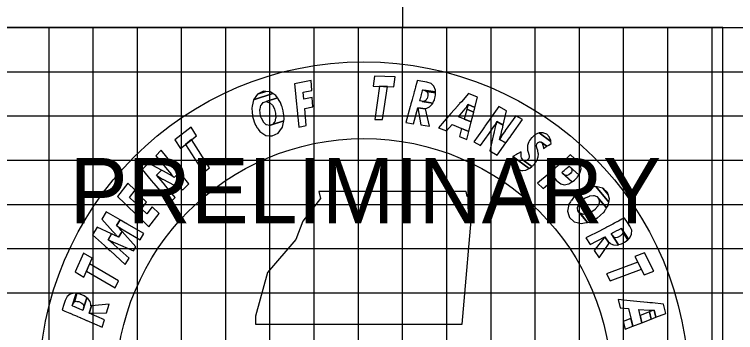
# Model space of a CAD drawing. Extents: x 21502 to 21854, y 6226 to 6446.
# Drawn here: x 21825.23 to 21841.55, y 6426.29 to 6433.48 of the extents above; entities that cross this region are included whole.
import ezdxf

# ---------------------------------------------------------------- set-up
doc = ezdxf.new("R2010")
doc.units = 0
for name, color, linetype in [('SHEET_LOGO', 7, 'Continuous'), ('SHEET_PRELIM', 7, 'Continuous'), ('SHEET_PROJ_NUMBER', 7, 'Continuous'), ('XS_SHEET_MAJOR_GRIDS', 7, 'Continuous'), ('XS_SHEET_MEDIUM_GRIDS', 7, 'Continuous'), ('XS_SHEET_MINOR_GRIDS', 7, 'Continuous')]:
    doc.layers.add(name, color=color, linetype=linetype)

msp = doc.modelspace()

# ---------------------------------------------------------------- linework, layer by layer
at = {"layer": 'SHEET_LOGO'}
for points in [[(21825.014, 6416.944), (21841.256, 6416.944), (21841.256, 6433.186), (21825.014, 6433.186)], [(21833.38, 6432.089), (21833.347, 6431.862), (21833.811, 6431.845), (21833.844, 6432.072)], [(21831.626, 6431.317), (21831.662, 6430.935), (21831.834, 6430.969), (21831.798, 6431.352), (21831.985, 6431.389), (21831.965, 6431.6), (21831.778, 6431.563), (21831.763, 6431.725), (21831.963, 6431.765), (21831.942, 6431.99), (21831.57, 6431.915), (21831.591, 6431.69), (21831.606, 6431.528)], [(21834.186, 6431.399), (21834.088, 6431.036), (21834.261, 6431.008), (21834.358, 6431.372), (21834.528, 6431.345), (21834.525, 6431.358), (21834.564, 6431.365), (21834.622, 6431.391), (21834.684, 6431.452), (21834.697, 6431.477), (21834.399, 6431.524), (21834.401, 6431.532), (21834.408, 6431.558), (21834.418, 6431.591), (21834.422, 6431.606), (21834.438, 6431.667), (21834.438, 6431.667), (21834.45, 6431.71), (21834.449, 6431.711), (21834.453, 6431.722), (21834.462, 6431.757), (21834.466, 6431.772), (21834.467, 6431.774), (21834.756, 6431.729), (21834.756, 6431.77), (21834.721, 6431.859), (21834.658, 6431.921), (21834.564, 6431.951), (21834.469, 6431.967), (21834.344, 6431.986), (21834.344, 6431.986), (21834.34, 6431.971), (21834.327, 6431.922), (21834.305, 6431.841), (21834.294, 6431.802), (21834.294, 6431.799), (21834.289, 6431.784), (21834.28, 6431.749), (21834.277, 6431.738), (21834.265, 6431.694), (21834.249, 6431.634), (21834.245, 6431.619), (21834.236, 6431.585), (21834.229, 6431.559), (21834.227, 6431.552), (21834.22, 6431.525), (21834.202, 6431.457), (21834.193, 6431.424), (21834.189, 6431.411)], [(21833.493, 6431.857), (21833.385, 6431.109), (21833.561, 6431.103), (21833.67, 6431.85)], [(21834.525, 6431.763), (21834.562, 6431.741), (21834.757, 6431.71), (21834.756, 6431.726), (21834.756, 6431.729), (21834.492, 6431.77)], [(21831.016, 6430.737), (21831.065, 6430.733), (21831.199, 6430.797), (21831.235, 6430.848), (21831.293, 6430.93), (21831.308, 6431.004), (21831.323, 6431.073), (21831.001, 6430.967), (21831.001, 6430.967), (21830.937, 6430.983), (21830.93, 6430.985), (21830.928, 6430.986), (21830.866, 6431.044), (21830.865, 6431.046), (21830.863, 6431.049), (21830.818, 6431.132), (21830.817, 6431.136), (21830.815, 6431.141), (21830.791, 6431.23), (21830.79, 6431.235), (21830.79, 6431.239), (21830.786, 6431.335), (21830.787, 6431.339), (21830.788, 6431.341), (21830.809, 6431.426), (21830.81, 6431.426), (21830.818, 6431.436), (21830.861, 6431.487), (21830.928, 6431.51), (21831.182, 6431.593), (21831.147, 6431.645), (21831.078, 6431.691), (21830.637, 6431.547), (21830.622, 6431.473), (21830.608, 6431.404), (21830.608, 6431.404), (21830.6, 6431.365), (21830.601, 6431.358), (21830.601, 6431.357), (21830.608, 6431.282), (21830.608, 6431.28), (21830.608, 6431.277), (21830.616, 6431.182), (21830.617, 6431.178), (21830.617, 6431.172), (21830.647, 6431.086), (21830.648, 6431.081), (21830.65, 6431.077), (21830.68, 6430.989), (21830.681, 6430.985), (21830.682, 6430.983), (21830.725, 6430.92), (21830.727, 6430.918), (21830.729, 6430.914), (21830.749, 6430.885), (21830.749, 6430.884), (21830.785, 6430.832), (21830.853, 6430.786), (21830.916, 6430.743)], [(21830.694, 6431.627), (21830.637, 6431.547), (21831.078, 6431.691), (21831.016, 6431.732), (21830.916, 6431.741), (21830.732, 6431.68)], [(21830.867, 6431.744), (21830.732, 6431.68), (21830.916, 6431.741), (21830.867, 6431.744)], [(21831.111, 6431.04), (21831.069, 6430.99), (21831.323, 6431.073), (21831.331, 6431.112), (21831.33, 6431.116), (21831.33, 6431.119), (21831.324, 6431.194), (21831.323, 6431.196), (21831.323, 6431.196), (21831.323, 6431.2), (21831.314, 6431.296), (21831.314, 6431.299), (21831.314, 6431.305), (21831.285, 6431.392), (21831.283, 6431.397), (21831.282, 6431.401), (21831.252, 6431.488), (21831.251, 6431.492), (21831.25, 6431.493), (21831.207, 6431.556), (21831.207, 6431.557), (21831.203, 6431.563), (21831.182, 6431.593), (21831.182, 6431.593), (21830.928, 6431.51), (21830.929, 6431.509), (21830.989, 6431.492), (21831.001, 6431.489), (21831.002, 6431.489), (21831.066, 6431.432), (21831.066, 6431.431), (21831.068, 6431.428), (21831.113, 6431.345), (21831.114, 6431.341), (21831.115, 6431.336), (21831.138, 6431.247), (21831.139, 6431.242), (21831.14, 6431.238), (21831.142, 6431.141), (21831.141, 6431.136), (21831.14, 6431.134), (21831.119, 6431.049), (21831.116, 6431.046)], [(21834.498, 6431.516), (21834.454, 6431.516), (21834.697, 6431.477), (21834.701, 6431.484), (21834.714, 6431.509), (21834.731, 6431.542), (21834.735, 6431.557), (21834.748, 6431.618), (21834.758, 6431.662), (21834.758, 6431.673), (21834.757, 6431.71), (21834.562, 6431.741), (21834.581, 6431.701), (21834.581, 6431.69), (21834.583, 6431.644), (21834.567, 6431.584), (21834.557, 6431.569), (21834.537, 6431.537)], [(21834.955, 6431.066), (21834.827, 6430.919), (21835.003, 6430.846), (21835.132, 6430.992), (21835.509, 6430.835), (21835.564, 6431.049), (21835.277, 6431.168), (21835.428, 6431.348), (21835.43, 6431.352), (21835.464, 6431.395), (21835.465, 6431.396), (21835.499, 6431.443), (21835.65, 6431.38), (21835.71, 6431.612), (21835.507, 6431.696), (21835.342, 6431.508), (21835.303, 6431.464), (21835.302, 6431.463), (21835.265, 6431.42), (21835.263, 6431.417), (21835.107, 6431.239)], [(21835.48, 6431.389), (21835.465, 6431.337), (21835.622, 6431.272), (21835.635, 6431.324), (21835.636, 6431.325), (21835.65, 6431.38), (21835.499, 6431.443), (21835.48, 6431.39)], [(21834.358, 6431.372), (21834.425, 6430.982), (21834.623, 6430.951), (21834.528, 6431.345)], [(21835.464, 6431.334), (21835.405, 6431.115), (21835.564, 6431.049), (21835.621, 6431.268), (21835.622, 6431.272), (21835.465, 6431.337)], [(21835.817, 6430.875), (21835.621, 6430.6), (21835.774, 6430.514), (21835.968, 6430.79), (21835.968, 6430.79), (21836.016, 6430.858), (21836.022, 6430.867), (21836.06, 6430.921), (21836.062, 6430.924), (21836.099, 6430.979), (21836.106, 6430.988), (21836.147, 6431.059), (21836.289, 6430.979), (21836.367, 6431.304), (21836.193, 6431.402), (21836.005, 6431.139), (21835.957, 6431.071), (21835.951, 6431.062), (21835.912, 6431.008), (21835.91, 6431.006), (21835.872, 6430.951), (21835.865, 6430.943)], [(21836.247, 6430.728), (21836.205, 6430.656), (21836.35, 6430.575), (21836.398, 6430.643), (21836.404, 6430.652), (21836.443, 6430.706), (21836.444, 6430.708), (21836.483, 6430.763), (21836.489, 6430.771), (21836.725, 6431.102), (21836.572, 6431.188), (21836.337, 6430.857), (21836.331, 6430.849), (21836.292, 6430.794), (21836.29, 6430.792), (21836.253, 6430.737)], [(21831.069, 6430.99), (21831.001, 6430.967), (21831.323, 6431.073), (21831.323, 6431.073)], [(21836.064, 6430.736), (21835.985, 6430.395), (21836.154, 6430.3), (21836.35, 6430.575), (21836.205, 6430.656), (21836.231, 6430.737), (21836.234, 6430.747), (21836.25, 6430.814), (21836.251, 6430.817), (21836.267, 6430.884), (21836.27, 6430.895), (21836.289, 6430.979), (21836.147, 6431.059), (21836.121, 6430.979), (21836.118, 6430.968), (21836.102, 6430.901), (21836.101, 6430.898), (21836.086, 6430.831), (21836.083, 6430.82)], [(21828.863, 6430.643), (21828.986, 6430.45), (21829.349, 6430.739), (21829.226, 6430.933)], [(21835.345, 6430.904), (21835.298, 6430.723), (21835.463, 6430.654), (21835.509, 6430.835)], [(21836.787, 6430.165), (21836.739, 6430.184), (21836.936, 6430.04), (21836.947, 6430.049), (21836.952, 6430.054), (21836.969, 6430.067), (21836.976, 6430.077), (21836.986, 6430.089), (21837.008, 6430.118), (21837.032, 6430.15), (21837.036, 6430.154), (21837.047, 6430.18), (21837.062, 6430.211), (21837.076, 6430.243), (21837.077, 6430.254), (21837.084, 6430.325), (21837.082, 6430.334), (21837.07, 6430.406), (21837.051, 6430.468), (21837.05, 6430.47), (21837.043, 6430.513), (21837.05, 6430.552), (21837.053, 6430.556), (21837.073, 6430.581), (21837.073, 6430.581), (21837.075, 6430.583), (21837.079, 6430.585), (21837.112, 6430.602), (21837.126, 6430.599), (21837.126, 6430.599), (21837.15, 6430.595), (21837.279, 6430.501), (21837.321, 6430.528), (21837.373, 6430.561), (21837.367, 6430.604), (21837.099, 6430.801), (21837.066, 6430.785), (21837.008, 6430.757), (21836.972, 6430.726), (21836.964, 6430.718), (21836.959, 6430.714), (21836.933, 6430.691), (21836.93, 6430.689), (21836.928, 6430.687), (21836.909, 6430.661), (21836.907, 6430.657), (21836.886, 6430.628), (21836.868, 6430.603), (21836.868, 6430.602), (21836.854, 6430.563), (21836.837, 6430.514), (21836.837, 6430.506), (21836.838, 6430.43), (21836.841, 6430.415), (21836.855, 6430.363), (21836.869, 6430.31), (21836.875, 6430.273), (21836.876, 6430.264), (21836.865, 6430.223), (21836.841, 6430.195), (21836.831, 6430.183), (21836.818, 6430.177), (21836.795, 6430.168)], [(21837.131, 6430.803), (21837.099, 6430.801), (21837.367, 6430.604), (21837.364, 6430.632), (21837.337, 6430.699), (21837.334, 6430.709), (21837.273, 6430.774), (21837.273, 6430.774), (21837.211, 6430.798), (21837.192, 6430.806)], [(21829.101, 6430.541), (21829.507, 6429.904), (21829.645, 6430.014), (21829.239, 6430.651)], [(21837.194, 6430.492), (21837.198, 6430.45), (21837.227, 6430.468), (21837.229, 6430.47), (21837.233, 6430.472), (21837.263, 6430.491), (21837.269, 6430.495), (21837.269, 6430.495), (21837.279, 6430.501), (21837.15, 6430.595), (21837.179, 6430.561), (21837.181, 6430.551), (21837.194, 6430.5), (21837.194, 6430.495)], [(21828.788, 6429.853), (21828.846, 6429.794), (21828.962, 6429.912), (21828.91, 6429.976), (21828.903, 6429.984), (21828.861, 6430.036), (21828.858, 6430.038), (21828.816, 6430.09), (21828.809, 6430.098), (21828.552, 6430.412), (21828.429, 6430.287), (21828.686, 6429.974), (21828.693, 6429.965), (21828.736, 6429.914), (21828.738, 6429.911), (21828.781, 6429.861)], [(21836.519, 6430.277), (21836.504, 6430.269), (21836.877, 6429.996), (21836.893, 6430.003), (21836.936, 6430.04), (21836.739, 6430.184), (21836.716, 6430.217), (21836.704, 6430.236), (21836.699, 6430.265), (21836.696, 6430.282), (21836.692, 6430.304), (21836.693, 6430.348), (21836.693, 6430.373), (21836.674, 6430.362), (21836.639, 6430.343), (21836.624, 6430.334), (21836.612, 6430.328), (21836.592, 6430.317), (21836.585, 6430.313), (21836.572, 6430.306)], [(21837.328, 6429.887), (21837.068, 6429.662), (21837.196, 6429.543), (21837.455, 6429.768), (21837.49, 6429.736), (21837.53, 6429.698), (21837.589, 6429.652), (21837.671, 6429.628), (21837.771, 6429.651), (21837.842, 6429.692), (21837.613, 6429.905), (21837.613, 6429.905), (21837.617, 6429.909), (21837.634, 6429.923), (21837.637, 6429.926), (21837.667, 6429.952), (21837.709, 6429.988), (21837.731, 6430.007), (21837.746, 6430.02), (21837.772, 6430.042), (21837.78, 6430.05), (21837.782, 6430.051), (21837.998, 6429.85), (21838.024, 6429.89), (21838.05, 6429.987), (21838.034, 6430.077), (21837.975, 6430.155), (21837.904, 6430.222), (21837.812, 6430.307), (21837.812, 6430.307), (21837.799, 6430.296), (21837.758, 6430.26), (21837.69, 6430.201), (21837.654, 6430.17), (21837.653, 6430.169), (21837.644, 6430.161), (21837.619, 6430.14), (21837.604, 6430.126), (21837.582, 6430.107), (21837.54, 6430.071), (21837.509, 6430.045), (21837.507, 6430.042), (21837.49, 6430.028), (21837.485, 6430.024), (21837.485, 6430.024), (21837.426, 6429.972), (21837.361, 6429.916), (21837.332, 6429.891), (21837.328, 6429.887)], [(21836.553, 6430.036), (21836.62, 6429.983), (21836.633, 6429.978), (21836.702, 6429.952), (21836.73, 6429.954), (21836.799, 6429.958), (21836.817, 6429.967), (21836.877, 6429.995), (21836.504, 6430.268), (21836.5, 6430.199), (21836.504, 6430.174), (21836.514, 6430.112), (21836.532, 6430.077)], [(21828.533, 6429.477), (21828.747, 6429.216), (21828.871, 6429.341), (21828.655, 6429.6), (21828.655, 6429.6), (21828.602, 6429.664), (21828.595, 6429.672), (21828.552, 6429.724), (21828.55, 6429.726), (21828.507, 6429.776), (21828.5, 6429.785), (21828.442, 6429.843), (21828.557, 6429.96), (21828.264, 6430.12), (21828.123, 6429.978), (21828.328, 6429.728), (21828.38, 6429.663), (21828.387, 6429.655), (21828.429, 6429.603), (21828.431, 6429.601), (21828.474, 6429.549), (21828.48, 6429.541)], [(21837.729, 6429.835), (21837.688, 6429.842), (21837.847, 6429.694), (21837.867, 6429.706), (21837.87, 6429.708), (21837.899, 6429.736), (21837.939, 6429.774), (21837.96, 6429.794), (21837.971, 6429.811), (21837.99, 6429.839), (21837.997, 6429.848), (21837.998, 6429.85), (21837.805, 6430.03), (21837.828, 6430.006), (21837.844, 6429.975), (21837.843, 6429.93), (21837.833, 6429.913), (21837.818, 6429.888), (21837.775, 6429.851), (21837.733, 6429.837)], [(21828.732, 6429.678), (21829.04, 6429.513), (21829.176, 6429.65), (21828.962, 6429.912), (21828.846, 6429.794), (21828.775, 6429.84), (21828.766, 6429.846), (21828.706, 6429.879), (21828.703, 6429.88), (21828.642, 6429.913), (21828.632, 6429.919), (21828.557, 6429.96), (21828.442, 6429.843), (21828.513, 6429.798), (21828.522, 6429.792), (21828.582, 6429.759), (21828.585, 6429.757), (21828.646, 6429.724), (21828.656, 6429.719)], [(21837.655, 6429.866), (21837.625, 6429.893), (21837.842, 6429.692), (21837.842, 6429.692), (21837.847, 6429.694), (21837.688, 6429.842)], [(21828.115, 6428.832), (21828.273, 6428.68), (21828.505, 6428.979), (21828.347, 6429.131), (21828.223, 6428.971), (21828.105, 6429.085), (21828.221, 6429.234), (21828.067, 6429.382), (21827.951, 6429.233), (21827.835, 6429.344), (21827.959, 6429.505), (21827.796, 6429.662), (21827.563, 6429.363), (21827.727, 6429.205), (21827.843, 6429.094), (21827.997, 6428.946)], [(21835.607, 6429.34), (21835.471, 6429.366), (21835.454, 6429.476), (21832.119, 6429.476), (21832.153, 6429.315), (21831.755, 6428.807), (21831.594, 6428.392), (21830.959, 6427.647), (21830.688, 6426.657), (21830.688, 6426.479), (21835.361, 6426.479)], [(21837.773, 6428.937), (21837.788, 6428.891), (21837.897, 6428.79), (21837.959, 6428.776), (21838.056, 6428.753), (21838.13, 6428.766), (21838.199, 6428.779), (21837.981, 6429.037), (21837.981, 6429.038), (21837.971, 6429.102), (21837.97, 6429.11), (21837.971, 6429.113), (21838.001, 6429.191), (21838.003, 6429.193), (21838.005, 6429.196), (21838.065, 6429.269), (21838.068, 6429.272), (21838.072, 6429.275), (21838.146, 6429.33), (21838.15, 6429.333), (21838.154, 6429.335), (21838.242, 6429.374), (21838.246, 6429.375), (21838.247, 6429.375), (21838.334, 6429.387), (21838.335, 6429.387), (21838.347, 6429.383), (21838.41, 6429.362), (21838.456, 6429.308), (21838.629, 6429.104), (21838.664, 6429.157), (21838.681, 6429.238), (21838.382, 6429.592), (21838.308, 6429.578), (21838.239, 6429.565), (21838.239, 6429.565), (21838.199, 6429.558), (21838.193, 6429.555), (21838.192, 6429.555), (21838.125, 6429.52), (21838.124, 6429.519), (21838.12, 6429.518), (21838.036, 6429.475), (21838.032, 6429.472), (21838.027, 6429.47), (21837.958, 6429.41), (21837.954, 6429.407), (21837.951, 6429.404), (21837.88, 6429.344), (21837.878, 6429.341), (21837.876, 6429.339), (21837.834, 6429.275), (21837.832, 6429.273), (21837.83, 6429.27), (21837.81, 6429.24), (21837.81, 6429.24), (21837.774, 6429.187), (21837.757, 6429.106), (21837.742, 6429.032)], [(21838.477, 6429.569), (21838.382, 6429.592), (21838.681, 6429.238), (21838.696, 6429.311), (21838.666, 6429.407), (21838.541, 6429.554)], [(21838.651, 6429.453), (21838.541, 6429.554), (21838.666, 6429.407), (21838.651, 6429.453)], [(21838.089, 6428.963), (21838.027, 6428.983), (21838.199, 6428.779), (21838.239, 6428.786), (21838.242, 6428.788), (21838.245, 6428.789), (21838.312, 6428.824), (21838.314, 6428.825), (21838.314, 6428.825), (21838.318, 6428.826), (21838.403, 6428.87), (21838.406, 6428.872), (21838.411, 6428.874), (21838.481, 6428.934), (21838.485, 6428.937), (21838.488, 6428.94), (21838.558, 6429), (21838.561, 6429.003), (21838.562, 6429.004), (21838.604, 6429.067), (21838.605, 6429.068), (21838.608, 6429.074), (21838.629, 6429.104), (21838.629, 6429.104), (21838.456, 6429.308), (21838.456, 6429.308), (21838.463, 6429.245), (21838.465, 6429.233), (21838.465, 6429.232), (21838.436, 6429.152), (21838.435, 6429.151), (21838.433, 6429.148), (21838.373, 6429.076), (21838.37, 6429.073), (21838.366, 6429.07), (21838.292, 6429.015), (21838.287, 6429.012), (21838.284, 6429.011), (21838.195, 6428.972), (21838.19, 6428.971), (21838.188, 6428.971), (21838.101, 6428.959), (21838.097, 6428.961)], [(21827.572, 6428.456), (21827.587, 6428.441), (21827.667, 6428.573), (21827.652, 6428.59), (21827.652, 6428.589), (21827.647, 6428.595), (21827.646, 6428.597), (21827.616, 6428.63), (21827.611, 6428.637), (21827.611, 6428.636), (21827.601, 6428.647), (21827.601, 6428.647), (21827.599, 6428.649), (21827.598, 6428.65), (21827.597, 6428.651), (21827.597, 6428.651), (21827.562, 6428.686), (21827.558, 6428.69), (21827.542, 6428.706), (21827.62, 6428.834), (21827.31, 6429.014), (21827.21, 6428.847), (21827.461, 6428.57), (21827.476, 6428.553), (21827.48, 6428.549), (21827.514, 6428.513), (21827.515, 6428.512), (21827.516, 6428.511), (21827.518, 6428.508), (21827.527, 6428.498), (21827.533, 6428.492), (21827.565, 6428.462), (21827.567, 6428.461)], [(21838.027, 6428.983), (21837.981, 6429.037), (21838.199, 6428.779), (21838.199, 6428.779)], [(21827.69, 6428.612), (21828.074, 6428.384), (21828.158, 6428.523), (21827.771, 6428.747), (21827.753, 6428.757), (21827.747, 6428.761), (21827.745, 6428.762), (21827.745, 6428.762), (21827.708, 6428.783), (21827.701, 6428.787), (21827.69, 6428.794), (21827.687, 6428.795), (21827.686, 6428.796), (21827.685, 6428.797), (21827.643, 6428.821), (21827.639, 6428.823), (21827.62, 6428.834), (21827.542, 6428.706), (21827.561, 6428.694), (21827.565, 6428.691), (21827.605, 6428.665), (21827.606, 6428.664), (21827.607, 6428.663), (21827.61, 6428.662), (21827.621, 6428.655), (21827.628, 6428.65), (21827.664, 6428.628), (21827.667, 6428.627), (21827.672, 6428.623)], [(21838.494, 6428.598), (21838.16, 6428.425), (21838.256, 6428.279), (21838.59, 6428.452), (21838.685, 6428.309), (21838.692, 6428.32), (21838.724, 6428.296), (21838.782, 6428.27), (21838.869, 6428.266), (21838.897, 6428.273), (21838.731, 6428.525), (21838.737, 6428.528), (21838.761, 6428.541), (21838.792, 6428.557), (21838.806, 6428.564), (21838.862, 6428.592), (21838.862, 6428.593), (21838.902, 6428.613), (21838.902, 6428.613), (21838.912, 6428.619), (21838.945, 6428.635), (21838.959, 6428.643), (21838.961, 6428.644), (21839.122, 6428.399), (21839.152, 6428.427), (21839.195, 6428.513), (21839.197, 6428.601), (21839.157, 6428.691), (21839.104, 6428.772), (21839.035, 6428.877), (21839.034, 6428.877), (21839.02, 6428.87), (21838.975, 6428.847), (21838.901, 6428.808), (21838.865, 6428.789), (21838.862, 6428.788), (21838.848, 6428.781), (21838.816, 6428.764), (21838.806, 6428.759), (21838.766, 6428.738), (21838.71, 6428.71), (21838.696, 6428.702), (21838.665, 6428.686), (21838.641, 6428.674), (21838.634, 6428.671), (21838.61, 6428.658), (21838.548, 6428.626), (21838.517, 6428.61), (21838.505, 6428.604)], [(21827.401, 6428.131), (21827.736, 6427.822), (21827.824, 6427.968), (21827.486, 6428.273), (21827.47, 6428.287), (21827.465, 6428.291), (21827.465, 6428.291), (21827.463, 6428.293), (21827.463, 6428.293), (21827.43, 6428.321), (21827.424, 6428.326), (21827.414, 6428.335), (21827.411, 6428.337), (21827.41, 6428.338), (21827.409, 6428.339), (21827.371, 6428.369), (21827.367, 6428.372), (21827.35, 6428.386), (21827.429, 6428.517), (21827.101, 6428.666), (21827.001, 6428.499), (21827.269, 6428.252), (21827.286, 6428.237), (21827.29, 6428.233), (21827.326, 6428.2), (21827.327, 6428.199), (21827.328, 6428.198), (21827.33, 6428.196), (21827.34, 6428.187), (21827.346, 6428.181), (21827.378, 6428.152), (21827.38, 6428.15), (21827.385, 6428.145)], [(21827.509, 6428.312), (21827.922, 6428.131), (21827.977, 6428.223), (21827.667, 6428.573), (21827.587, 6428.441), (21827.569, 6428.451), (21827.562, 6428.454), (21827.56, 6428.455), (21827.522, 6428.474), (21827.515, 6428.477), (21827.503, 6428.483), (21827.5, 6428.484), (21827.499, 6428.485), (21827.498, 6428.485), (21827.454, 6428.506), (21827.449, 6428.508), (21827.429, 6428.517), (21827.35, 6428.386), (21827.37, 6428.376), (21827.374, 6428.374), (21827.418, 6428.353), (21827.419, 6428.352), (21827.42, 6428.352), (21827.423, 6428.35), (21827.435, 6428.345), (21827.442, 6428.342), (21827.481, 6428.324), (21827.484, 6428.323), (21827.49, 6428.32)], [(21838.791, 6428.447), (21838.761, 6428.479), (21838.897, 6428.273), (21838.905, 6428.275), (21838.932, 6428.282), (21838.967, 6428.292), (21838.981, 6428.299), (21839.035, 6428.33), (21839.074, 6428.353), (21839.082, 6428.361), (21839.109, 6428.386), (21839, 6428.551), (21838.984, 6428.51), (21838.975, 6428.502), (21838.942, 6428.47), (21838.887, 6428.441), (21838.87, 6428.438), (21838.833, 6428.432)], [(21838.991, 6428.593), (21839, 6428.551), (21839.109, 6428.386), (21839.12, 6428.397), (21839.122, 6428.399), (21838.975, 6428.622)], [(21838.59, 6428.452), (21838.348, 6428.14), (21838.458, 6427.973), (21838.685, 6428.309)], [(21826.602, 6427.658), (21826.8, 6427.542), (21826.99, 6427.965), (21826.792, 6428.081)], [(21839.485, 6428.089), (21839.27, 6428.009), (21839.478, 6427.594), (21839.693, 6427.674)], [(21839.335, 6427.878), (21838.628, 6427.612), (21838.707, 6427.455), (21839.415, 6427.72)], [(21826.86, 6427.675), (21827.512, 6427.295), (21827.585, 6427.456), (21826.932, 6427.837)], [(21826.87, 6426.557), (21827.215, 6426.407), (21827.267, 6426.574), (21826.922, 6426.724), (21826.974, 6426.888), (21826.96, 6426.887), (21826.959, 6426.926), (21826.942, 6426.987), (21826.891, 6427.057), (21826.867, 6427.074), (21826.777, 6426.787), (21826.77, 6426.79), (21826.746, 6426.8), (21826.713, 6426.814), (21826.699, 6426.821), (21826.642, 6426.846), (21826.642, 6426.846), (21826.6, 6426.864), (21826.6, 6426.864), (21826.59, 6426.868), (21826.556, 6426.883), (21826.542, 6426.889), (21826.54, 6426.89), (21826.627, 6427.17), (21826.587, 6427.175), (21826.493, 6427.154), (21826.423, 6427.1), (21826.379, 6427.012), (21826.35, 6426.92), (21826.312, 6426.8), (21826.312, 6426.799), (21826.327, 6426.793), (21826.374, 6426.773), (21826.45, 6426.74), (21826.487, 6426.723), (21826.49, 6426.722), (21826.504, 6426.716), (21826.538, 6426.701), (21826.548, 6426.697), (21826.59, 6426.679), (21826.647, 6426.654), (21826.661, 6426.648), (21826.693, 6426.634), (21826.718, 6426.623), (21826.725, 6426.62), (21826.75, 6426.609), (21826.815, 6426.581), (21826.847, 6426.567), (21826.858, 6426.562)], [(21826.56, 6426.946), (21826.587, 6426.979), (21826.646, 6427.168), (21826.63, 6427.169), (21826.627, 6427.17), (21826.547, 6426.915)], [(21826.799, 6426.883), (21826.794, 6426.839), (21826.867, 6427.074), (21826.861, 6427.079), (21826.838, 6427.096), (21826.809, 6427.117), (21826.794, 6427.123), (21826.736, 6427.145), (21826.694, 6427.162), (21826.682, 6427.163), (21826.646, 6427.168), (21826.587, 6426.979), (21826.629, 6426.992), (21826.64, 6426.991), (21826.686, 6426.985), (21826.743, 6426.961), (21826.756, 6426.95), (21826.785, 6426.925)], [(21839.084, 6427.013), (21838.889, 6427.031), (21838.932, 6426.845), (21839.127, 6426.826), (21839.219, 6426.428), (21839.424, 6426.507), (21839.354, 6426.81), (21839.589, 6426.793), (21839.593, 6426.793), (21839.648, 6426.791), (21839.649, 6426.791), (21839.707, 6426.79), (21839.744, 6426.631), (21839.967, 6426.717), (21839.918, 6426.931), (21839.668, 6426.955), (21839.61, 6426.961), (21839.608, 6426.961), (21839.552, 6426.967), (21839.548, 6426.967), (21839.313, 6426.99)], [(21826.922, 6426.724), (21827.317, 6426.733), (21827.377, 6426.924), (21826.974, 6426.888)], [(21839.597, 6426.755), (21839.386, 6426.675), (21839.424, 6426.507), (21839.636, 6426.589), (21839.639, 6426.59), (21839.601, 6426.756)], [(21839.652, 6426.774), (21839.601, 6426.756), (21839.639, 6426.59), (21839.69, 6426.61), (21839.691, 6426.61), (21839.744, 6426.63), (21839.707, 6426.79), (21839.653, 6426.774)], [(21839.179, 6426.602), (21839.004, 6426.534), (21839.045, 6426.36), (21839.219, 6426.428)]]:
    msp.add_lwpolyline(points, close=True, dxfattribs=at)
for radius in [7.347, 5.608]:
    msp.add_circle((21833.135, 6425.065), radius, dxfattribs=at)
at = {"layer": 'SHEET_PRELIM'}
msp.add_lwpolyline([(21825.014, 6416.944), (21841.256, 6416.944), (21841.256, 6433.186), (21825.014, 6433.186)], close=True, dxfattribs=at)
at = {"layer": 'SHEET_PROJ_NUMBER'}
for p, q in [((21834.013, 6441.186), (21834.013, 6433.186)), ((21825.014, 6433.186), (21852.013, 6433.186))]:
    msp.add_line(p, q, dxfattribs=at)
at = {"layer": 'XS_SHEET_MAJOR_GRIDS'}
for p, q in [((21832.013, 6231.187), (21832.013, 6433.186)), ((21517.014, 6431.186), (21852.013, 6431.186))]:
    msp.add_line(p, q, dxfattribs=at)
at = {"layer": 'XS_SHEET_MEDIUM_GRIDS'}
for p, q in [((21827.014, 6231.187), (21827.014, 6433.186)), ((21837.013, 6231.187), (21837.013, 6433.186))]:
    msp.add_line(p, q, dxfattribs=at)
at = {"layer": 'XS_SHEET_MINOR_GRIDS'}
for p, q in [((21826.014, 6231.187), (21826.014, 6433.186)), ((21828.014, 6231.187), (21828.014, 6433.186)), ((21829.014, 6231.187), (21829.014, 6433.186)), ((21830.014, 6231.187), (21830.014, 6433.186)), ((21831.013, 6231.187), (21831.013, 6433.186)), ((21833.013, 6231.187), (21833.013, 6433.186)), ((21834.013, 6231.187), (21834.013, 6433.186)), ((21835.013, 6231.187), (21835.013, 6433.186)), ((21836.013, 6231.187), (21836.013, 6433.186)), ((21838.013, 6231.187), (21838.013, 6433.186)), ((21839.013, 6231.187), (21839.013, 6433.186)), ((21840.013, 6231.187), (21840.013, 6433.186)), ((21841.013, 6231.187), (21841.013, 6433.186)), ((21517.014, 6432.186), (21852.013, 6432.186)), ((21517.014, 6430.186), (21852.013, 6430.186)), ((21517.014, 6429.186), (21852.013, 6429.186)), ((21517.014, 6428.186), (21852.013, 6428.186)), ((21517.014, 6427.186), (21852.013, 6427.186))]:
    msp.add_line(p, q, dxfattribs=at)

# ---------------------------------------------------------------- texts
at = {"layer": 'SHEET_PRELIM'}
msp.add_text('PRELIMINARY', height=1.47661, dxfattribs=at).set_placement((21826.476, 6428.756))

doc.saveas('drawing.dxf')
